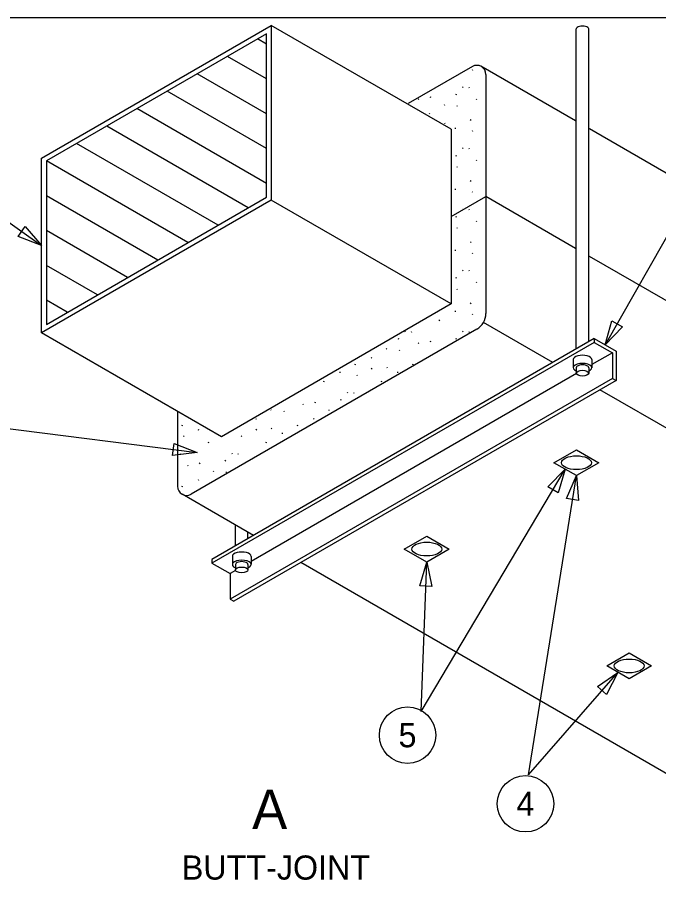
# Model space of a CAD drawing. Extents: x 10110.2 to 10159.4, y 10049.5 to 10140.5.
# Drawn here: x 10126.8 to 10144.51, y 10116.52 to 10140.51 of the extents above; entities that cross this region are included whole.
import ezdxf

# ---------------------------------------------------------------- set-up
doc = ezdxf.new("R2010")
doc.units = 0
for name, color, linetype in [('G-ANNO-SYMB', 7, 'Continuous'), ('G-DETL-GRID', 7, 'Continuous'), ('G-DETL-LINE', 7, 'Continuous'), ('G-DETL-TEXT', 7, 'Continuous')]:
    doc.layers.add(name, color=color, linetype=linetype)

msp = doc.modelspace()

# ---------------------------------------------------------------- linework, layer by layer
at = {"layer": 'G-ANNO-SYMB'}
for centre in [(10137.574, 10120.68), (10140.832, 10118.787)]:
    msp.add_circle(centre, 0.779, dxfattribs=at)
at = {"layer": 'G-DETL-GRID'}
msp.add_lwpolyline([(10110.22, 10140.505), (10159.362, 10140.505), (10159.362, 10095.005), (10110.22, 10095.005)], close=True, dxfattribs=at)
at = {"layer": 'G-DETL-LINE'}
for p, q in [((10138.779, 10137.415), (10133.81, 10140.284)), ((10138.779, 10137.415), (10133.81, 10140.284)), ((10142.233, 10131.347), (10142.233, 10140.184)), ((10142.233, 10131.347), (10142.233, 10140.184)), ((10142.578, 10131.546), (10142.578, 10140.184)), ((10142.578, 10131.546), (10142.578, 10140.184)), ((10133.675, 10139.767), (10133.431, 10139.908)), ((10133.675, 10138.805), (10132.597, 10139.427)), ((10139.363, 10139.147), (10137.591, 10138.124)), ((10139.363, 10139.147), (10137.591, 10138.124)), ((10142.214, 10137.645), (10139.598, 10139.156)), ((10142.214, 10137.645), (10139.598, 10139.156)), ((10133.675, 10137.843), (10131.764, 10138.946)), ((10139.359, 10139.064), (10139.371, 10139.046)), ((10139.359, 10139.064), (10139.371, 10139.046)), ((10139.738, 10138.93), (10139.738, 10132.325)), ((10139.738, 10138.93), (10139.738, 10132.325)), ((10133.675, 10136.88), (10130.931, 10138.465)), ((10138.917, 10138.363), (10138.929, 10138.39)), ((10138.917, 10138.363), (10138.929, 10138.39)), ((10139.094, 10138.585), (10139.106, 10138.567)), ((10139.094, 10138.585), (10139.106, 10138.567)), ((10139.264, 10138.578), (10139.276, 10138.56)), ((10139.264, 10138.578), (10139.276, 10138.56)), ((10137.871, 10138.259), (10137.883, 10138.241)), ((10137.871, 10138.259), (10137.883, 10138.241)), ((10138.207, 10138.294), (10138.219, 10138.321)), ((10138.207, 10138.294), (10138.219, 10138.321)), ((10139.465, 10138.259), (10139.477, 10138.241)), ((10139.465, 10138.259), (10139.477, 10138.241)), ((10133.675, 10135.918), (10130.097, 10137.984)), ((10138.581, 10138.102), (10138.593, 10138.084)), ((10138.581, 10138.102), (10138.593, 10138.084)), ((10138.935, 10138.069), (10138.947, 10138.051)), ((10138.935, 10138.069), (10138.947, 10138.051)), ((10138.167, 10137.857), (10138.179, 10137.839)), ((10138.167, 10137.857), (10138.179, 10137.839)), ((10139.315, 10137.655), (10139.327, 10137.682)), ((10139.315, 10137.655), (10139.327, 10137.682)), ((10133.173, 10135.246), (10129.264, 10137.503)), ((10138.592, 10137.591), (10138.604, 10137.573)), ((10138.592, 10137.591), (10138.604, 10137.573)), ((10138.889, 10137.457), (10138.892, 10137.43)), ((10138.889, 10137.457), (10138.892, 10137.43)), ((10148.395, 10134.077), (10142.598, 10137.424)), ((10148.395, 10134.077), (10142.598, 10137.424)), ((10138.779, 10137.415), (10138.779, 10132.589)), ((10138.779, 10137.415), (10138.779, 10132.589)), ((10139.359, 10137.378), (10139.371, 10137.36)), ((10139.359, 10137.378), (10139.371, 10137.36)), ((10132.339, 10134.765), (10128.431, 10137.021)), ((10138.917, 10136.676), (10138.929, 10136.703)), ((10138.917, 10136.676), (10138.929, 10136.703)), ((10139.094, 10136.898), (10139.106, 10136.88)), ((10139.094, 10136.898), (10139.106, 10136.88)), ((10139.264, 10136.892), (10139.276, 10136.874)), ((10139.264, 10136.892), (10139.276, 10136.874)), ((10131.506, 10134.284), (10127.597, 10136.54)), ((10139.465, 10136.572), (10139.477, 10136.554)), ((10139.465, 10136.572), (10139.477, 10136.554)), ((10138.935, 10136.383), (10138.947, 10136.365)), ((10138.935, 10136.383), (10138.947, 10136.365)), ((10139.315, 10135.969), (10139.327, 10135.996)), ((10139.315, 10135.969), (10139.327, 10135.996)), ((10138.889, 10135.771), (10138.892, 10135.744)), ((10138.889, 10135.771), (10138.892, 10135.744)), ((10130.673, 10133.803), (10127.597, 10135.578)), ((10138.779, 10135.002), (10139.738, 10135.555)), ((10138.779, 10135.002), (10139.738, 10135.555)), ((10139.359, 10135.691), (10139.371, 10135.673)), ((10139.359, 10135.691), (10139.371, 10135.673)), ((10142.214, 10134.125), (10139.738, 10135.555)), ((10142.214, 10134.125), (10139.738, 10135.555)), ((10138.779, 10132.589), (10133.81, 10135.458)), ((10138.779, 10132.589), (10133.81, 10135.458)), ((10139.094, 10135.212), (10139.106, 10135.194)), ((10139.094, 10135.212), (10139.106, 10135.194)), ((10139.264, 10135.205), (10139.276, 10135.187)), ((10139.264, 10135.205), (10139.276, 10135.187)), ((10138.917, 10134.99), (10138.929, 10135.017)), ((10138.917, 10134.99), (10138.929, 10135.017)), ((10139.465, 10134.886), (10139.477, 10134.868)), ((10139.465, 10134.886), (10139.477, 10134.868)), ((10129.839, 10133.321), (10127.597, 10134.616)), ((10138.935, 10134.697), (10138.947, 10134.679)), ((10138.935, 10134.697), (10138.947, 10134.679)), ((10139.315, 10134.283), (10139.327, 10134.31)), ((10139.315, 10134.283), (10139.327, 10134.31)), ((10138.889, 10134.085), (10138.892, 10134.058)), ((10138.889, 10134.085), (10138.892, 10134.058)), ((10139.359, 10134.005), (10139.371, 10133.987)), ((10139.359, 10134.005), (10139.371, 10133.987)), ((10148.947, 10130.239), (10142.598, 10133.904)), ((10148.947, 10130.239), (10142.598, 10133.904)), ((10129.006, 10132.84), (10127.597, 10133.654)), ((10139.094, 10133.526), (10139.106, 10133.508)), ((10139.094, 10133.526), (10139.106, 10133.508)), ((10139.264, 10133.519), (10139.276, 10133.501)), ((10139.264, 10133.519), (10139.276, 10133.501)), ((10138.917, 10133.304), (10138.929, 10133.331)), ((10138.917, 10133.304), (10138.929, 10133.331)), ((10139.465, 10133.2), (10139.477, 10133.182)), ((10139.465, 10133.2), (10139.477, 10133.182)), ((10138.935, 10133.011), (10138.947, 10132.993)), ((10138.935, 10133.011), (10138.947, 10132.993)), ((10128.173, 10132.359), (10127.597, 10132.691)), ((10139.315, 10132.596), (10139.327, 10132.623)), ((10139.315, 10132.596), (10139.327, 10132.623)), ((10138.779, 10132.589), (10132.431, 10128.924)), ((10138.779, 10132.589), (10132.431, 10128.924)), ((10138.889, 10132.398), (10138.892, 10132.371)), ((10138.889, 10132.398), (10138.892, 10132.371)), ((10138.449, 10132.126), (10138.461, 10132.153)), ((10138.449, 10132.126), (10138.461, 10132.153)), ((10139.359, 10132.319), (10139.371, 10132.301)), ((10139.359, 10132.319), (10139.371, 10132.301)), ((10141.582, 10130.971), (10139.671, 10132.075)), ((10141.582, 10130.971), (10139.671, 10132.075)), ((10132.431, 10128.924), (10127.462, 10131.793)), ((10132.431, 10128.924), (10127.462, 10131.793)), ((10139.488, 10131.892), (10131.597, 10127.336)), ((10139.488, 10131.892), (10131.597, 10127.336)), ((10137.499, 10131.84), (10137.511, 10131.822)), ((10137.499, 10131.84), (10137.511, 10131.822)), ((10137.67, 10131.833), (10137.682, 10131.815)), ((10137.67, 10131.833), (10137.682, 10131.815)), ((10139.094, 10131.84), (10139.106, 10131.822)), ((10139.094, 10131.84), (10139.106, 10131.822)), ((10139.264, 10131.833), (10139.276, 10131.815)), ((10139.264, 10131.833), (10139.276, 10131.815)), ((10142.73, 10131.633), (10132.17, 10125.536)), ((10142.73, 10131.633), (10132.17, 10125.536)), ((10142.73, 10131.529), (10132.17, 10125.432)), ((10142.73, 10131.529), (10132.17, 10125.432)), ((10137.322, 10131.617), (10137.334, 10131.644)), ((10137.322, 10131.617), (10137.334, 10131.644)), ((10137.871, 10131.513), (10137.883, 10131.495)), ((10137.871, 10131.513), (10137.883, 10131.495)), ((10138.207, 10131.548), (10138.219, 10131.575)), ((10138.207, 10131.548), (10138.219, 10131.575)), ((10138.917, 10131.617), (10138.929, 10131.644)), ((10138.917, 10131.617), (10138.929, 10131.644)), ((10142.73, 10131.633), (10143.334, 10131.284)), ((10142.73, 10131.633), (10142.73, 10131.529)), ((10142.73, 10131.633), (10143.334, 10131.284)), ((10142.73, 10131.633), (10142.73, 10131.529)), ((10142.73, 10131.529), (10143.23, 10131.24)), ((10142.73, 10131.529), (10143.23, 10131.24)), ((10136.987, 10131.357), (10136.999, 10131.339)), ((10136.987, 10131.357), (10136.999, 10131.339)), ((10137.341, 10131.324), (10137.353, 10131.306)), ((10137.341, 10131.324), (10137.353, 10131.306)), ((10143.23, 10131.24), (10142.665, 10130.914)), ((10143.23, 10131.24), (10142.665, 10130.914)), ((10143.23, 10131.24), (10143.23, 10130.534)), ((10143.23, 10131.24), (10143.23, 10130.534)), ((10143.334, 10131.284), (10143.334, 10130.474)), ((10143.334, 10131.284), (10143.334, 10130.474)), ((10136.572, 10131.111), (10136.584, 10131.093)), ((10136.572, 10131.111), (10136.584, 10131.093)), ((10142.147, 10131.054), (10142.147, 10130.829)), ((10142.147, 10131.054), (10142.147, 10130.829)), ((10142.665, 10131.054), (10142.665, 10130.829)), ((10142.665, 10131.054), (10142.665, 10130.829)), ((10135.7, 10130.712), (10135.703, 10130.685)), ((10135.7, 10130.712), (10135.703, 10130.685)), ((10136.127, 10130.91), (10136.139, 10130.937)), ((10136.127, 10130.91), (10136.139, 10130.937)), ((10136.582, 10130.787), (10136.594, 10130.814)), ((10136.582, 10130.787), (10136.594, 10130.814)), ((10136.998, 10130.845), (10137.01, 10130.827)), ((10136.998, 10130.845), (10137.01, 10130.827)), ((10137.295, 10130.712), (10137.298, 10130.685)), ((10137.295, 10130.712), (10137.298, 10130.685)), ((10137.721, 10130.91), (10137.733, 10130.937)), ((10137.721, 10130.91), (10137.733, 10130.937)), ((10142.233, 10130.829), (10142.233, 10130.679)), ((10142.233, 10130.829), (10142.233, 10130.679)), ((10142.578, 10130.829), (10142.578, 10130.679)), ((10142.578, 10130.829), (10142.578, 10130.679)), ((10143.23, 10130.534), (10132.67, 10124.438)), ((10143.23, 10130.534), (10132.67, 10124.438)), ((10143.334, 10130.474), (10132.774, 10124.377)), ((10143.334, 10130.474), (10132.774, 10124.377)), ((10142.236, 10130.666), (10133.252, 10125.48)), ((10142.236, 10130.666), (10133.252, 10125.48)), ((10135.261, 10130.44), (10135.273, 10130.466)), ((10135.261, 10130.44), (10135.273, 10130.466)), ((10136.17, 10130.632), (10136.182, 10130.614)), ((10136.17, 10130.632), (10136.182, 10130.614)), ((10136.855, 10130.44), (10136.867, 10130.466)), ((10136.855, 10130.44), (10136.867, 10130.466)), ((10143.23, 10130.534), (10143.334, 10130.474)), ((10143.23, 10130.534), (10143.334, 10130.474)), ((10135.905, 10130.153), (10135.917, 10130.135)), ((10135.905, 10130.153), (10135.917, 10130.135)), ((10136.076, 10130.146), (10136.088, 10130.128)), ((10136.076, 10130.146), (10136.088, 10130.128)), ((10156.935, 10122.107), (10142.888, 10130.217)), ((10156.935, 10122.107), (10142.888, 10130.217)), ((10134.682, 10129.827), (10134.694, 10129.809)), ((10134.682, 10129.827), (10134.694, 10129.809)), ((10135.018, 10129.862), (10135.03, 10129.889)), ((10135.018, 10129.862), (10135.03, 10129.889)), ((10135.728, 10129.931), (10135.74, 10129.958)), ((10135.728, 10129.931), (10135.74, 10129.958)), ((10131.222, 10129.621), (10131.222, 10127.553)), ((10131.222, 10129.621), (10131.222, 10127.553)), ((10133.798, 10129.67), (10133.81, 10129.652)), ((10133.798, 10129.67), (10133.81, 10129.652)), ((10134.152, 10129.638), (10134.164, 10129.62)), ((10134.152, 10129.638), (10134.164, 10129.62)), ((10135.392, 10129.67), (10135.404, 10129.652)), ((10135.392, 10129.67), (10135.404, 10129.652)), ((10133.384, 10129.425), (10133.396, 10129.407)), ((10133.384, 10129.425), (10133.396, 10129.407)), ((10134.978, 10129.425), (10134.99, 10129.407)), ((10134.978, 10129.425), (10134.99, 10129.407)), ((10131.344, 10129.224), (10131.356, 10129.251)), ((10131.344, 10129.224), (10131.356, 10129.251)), ((10131.799, 10129.101), (10131.811, 10129.128)), ((10131.799, 10129.101), (10131.811, 10129.128)), ((10133.394, 10129.101), (10133.406, 10129.128)), ((10133.394, 10129.101), (10133.406, 10129.128)), ((10133.809, 10129.159), (10133.821, 10129.141)), ((10133.809, 10129.159), (10133.821, 10129.141)), ((10134.106, 10129.026), (10134.109, 10128.999)), ((10134.106, 10129.026), (10134.109, 10128.999)), ((10134.532, 10129.224), (10134.544, 10129.251)), ((10134.532, 10129.224), (10134.544, 10129.251)), ((10131.387, 10128.946), (10131.399, 10128.928)), ((10131.387, 10128.946), (10131.399, 10128.928)), ((10132.982, 10128.946), (10132.994, 10128.928)), ((10132.982, 10128.946), (10132.994, 10128.928)), ((10132.072, 10128.753), (10132.084, 10128.78)), ((10132.072, 10128.753), (10132.084, 10128.78)), ((10133.666, 10128.753), (10133.678, 10128.78)), ((10133.666, 10128.753), (10133.678, 10128.78)), ((10131.293, 10128.46), (10131.305, 10128.442)), ((10131.293, 10128.46), (10131.305, 10128.442)), ((10132.716, 10128.467), (10132.728, 10128.449)), ((10132.716, 10128.467), (10132.728, 10128.449)), ((10132.887, 10128.46), (10132.899, 10128.442)), ((10132.887, 10128.46), (10132.899, 10128.442)), ((10131.494, 10128.141), (10131.506, 10128.123)), ((10131.494, 10128.141), (10131.506, 10128.123)), ((10131.829, 10128.176), (10131.841, 10128.203)), ((10131.829, 10128.176), (10131.841, 10128.203)), ((10132.539, 10128.245), (10132.551, 10128.272)), ((10132.539, 10128.245), (10132.551, 10128.272)), ((10132.204, 10127.984), (10132.216, 10127.966)), ((10132.204, 10127.984), (10132.216, 10127.966)), ((10132.558, 10127.952), (10132.57, 10127.934)), ((10132.558, 10127.952), (10132.57, 10127.934)), ((10131.789, 10127.739), (10131.801, 10127.721)), ((10131.789, 10127.739), (10131.801, 10127.721)), ((10131.344, 10127.537), (10131.356, 10127.564)), ((10131.344, 10127.537), (10131.356, 10127.564)), ((10133.317, 10126.199), (10131.347, 10127.337)), ((10133.317, 10126.199), (10131.347, 10127.337)), ((10132.821, 10125.912), (10132.821, 10126.485)), ((10132.821, 10125.912), (10132.821, 10126.485)), ((10133.166, 10126.112), (10133.166, 10126.286)), ((10133.166, 10126.112), (10133.166, 10126.286)), ((10132.17, 10125.536), (10132.17, 10125.432)), ((10132.17, 10125.536), (10132.17, 10125.432)), ((10132.17, 10125.536), (10132.17, 10125.432)), ((10132.17, 10125.536), (10132.17, 10125.432)), ((10132.17, 10125.432), (10132.67, 10125.144)), ((10132.17, 10125.432), (10132.67, 10125.144)), ((10132.735, 10125.619), (10132.735, 10125.394)), ((10132.735, 10125.619), (10132.735, 10125.394)), ((10133.252, 10125.619), (10133.252, 10125.394)), ((10133.252, 10125.619), (10133.252, 10125.394)), ((10148.487, 10117.44), (10134.623, 10125.445)), ((10148.487, 10117.44), (10134.623, 10125.445)), ((10132.823, 10125.232), (10132.67, 10125.144)), ((10132.823, 10125.232), (10132.67, 10125.144)), ((10132.821, 10125.394), (10132.821, 10125.244)), ((10132.821, 10125.394), (10132.821, 10125.244)), ((10133.166, 10125.394), (10133.166, 10125.244)), ((10133.166, 10125.394), (10133.166, 10125.244)), ((10132.67, 10125.144), (10132.67, 10124.438)), ((10132.67, 10125.144), (10132.67, 10124.438)), ((10132.67, 10124.438), (10132.774, 10124.377)), ((10132.67, 10124.438), (10132.774, 10124.377))]:
    msp.add_line(p, q, dxfattribs=at)
for points in [[(10127.462, 10136.618), (10133.81, 10140.284), (10133.81, 10135.458), (10127.462, 10131.793)], [(10127.462, 10136.618), (10133.81, 10140.284), (10133.81, 10135.458), (10127.462, 10131.793)], [(10127.597, 10136.54), (10127.597, 10132.027), (10133.675, 10135.536), (10133.675, 10140.049)], [(10127.597, 10136.54), (10127.597, 10132.027), (10133.675, 10135.536), (10133.675, 10140.049)], [(10141.617, 10128.206), (10142.238, 10128.565), (10142.859, 10128.206), (10142.238, 10127.848)], [(10141.617, 10128.206), (10142.238, 10128.565), (10142.859, 10128.206), (10142.238, 10127.848)], [(10137.484, 10125.82), (10138.105, 10126.179), (10138.726, 10125.82), (10138.105, 10125.462)], [(10137.484, 10125.82), (10138.105, 10126.179), (10138.726, 10125.82), (10138.105, 10125.462)], [(10143.074, 10122.593), (10143.695, 10122.952), (10144.316, 10122.593), (10143.695, 10122.234)], [(10143.074, 10122.593), (10143.695, 10122.952), (10144.316, 10122.593), (10143.695, 10122.234)]]:
    msp.add_lwpolyline(points, close=True, dxfattribs=at)
for centre, radius, start, end in [((10139.488, 10138.93), 0.25, 0, 120), ((10139.488, 10138.93), 0.25, 0, 120), ((10139.238, 10132.325), 0.5, 300, 0), ((10139.238, 10132.325), 0.5, 300, 0), ((10131.472, 10127.553), 0.25, 180, 300), ((10131.472, 10127.553), 0.25, 180, 300)]:
    msp.add_arc(centre, radius, start, end, dxfattribs=at)
for centre, major_axis, start_param, end_param in [((10142.406, 10140.185), (-0.173, 0), 3.137491, 6.287287), ((10142.406, 10140.185), (-0.173, 0), 3.137491, 6.287287), ((10142.406, 10130.829), (-0.259, 0), 2.300516, 7.124262), ((10142.406, 10130.829), (-0.259, 0), 2.300516, 7.124262), ((10142.406, 10131.054), (-0.259, 0), 3.137491, 6.287287), ((10142.406, 10131.054), (-0.259, 0), 3.137491, 6.287287), ((10142.406, 10130.829), (-0.173, 0), 3.137491, 6.287287), ((10142.406, 10130.829), (-0.173, 0), 3.137491, 6.287287), ((10132.993, 10125.619), (-0.259, 0), 3.137491, 6.287287), ((10132.993, 10125.619), (-0.259, 0), 3.137491, 6.287287), ((10132.993, 10125.394), (-0.259, 0), 2.300516, 7.124262), ((10132.993, 10125.394), (-0.259, 0), 2.300516, 7.124262), ((10132.993, 10125.394), (-0.173, 0), 3.137491, 6.287287), ((10132.993, 10125.394), (-0.173, 0), 3.137491, 6.287287)]:
    msp.add_ellipse(centre, major_axis=major_axis, ratio=0.460797, start_param=start_param, end_param=end_param, dxfattribs=at)
for centre, major_axis in [((10142.406, 10130.679), (-0.173, 0)), ((10142.406, 10130.679), (-0.173, 0)), ((10142.238, 10128.206), (-0.413, 0)), ((10142.238, 10128.206), (-0.413, 0)), ((10138.105, 10125.82), (-0.413, 0)), ((10138.105, 10125.82), (-0.413, 0)), ((10132.993, 10125.244), (-0.173, 0)), ((10132.993, 10125.244), (-0.173, 0)), ((10143.695, 10122.593), (-0.413, 0)), ((10143.695, 10122.593), (-0.413, 0))]:
    msp.add_ellipse(centre, major_axis=major_axis, ratio=0.460797, dxfattribs=at)
at = {"layer": 'G-DETL-TEXT'}
for p, q in [((10146.44, 10137.459), (10143.032, 10131.459)), ((10146.44, 10137.459), (10143.032, 10131.459)), ((10125.12, 10135.869), (10127.462, 10134.206)), ((10125.258, 10129.309), (10131.765, 10128.489)), ((10125.258, 10129.309), (10131.765, 10128.489)), ((10137.949, 10121.332), (10141.927, 10128.027)), ((10137.949, 10121.332), (10141.927, 10128.027)), ((10140.917, 10119.585), (10142.238, 10127.848)), ((10140.917, 10119.585), (10142.238, 10127.848)), ((10137.949, 10121.332), (10138.105, 10125.462)), ((10137.949, 10121.332), (10138.105, 10125.462)), ((10140.917, 10119.585), (10143.385, 10122.414))]:
    msp.add_line(p, q, dxfattribs=at)
for points in [[(10127.015, 10134.727), (10127.462, 10134.206), (10126.822, 10134.456)], [(10127.015, 10134.727), (10127.462, 10134.206), (10126.822, 10134.456)], [(10143.506, 10131.956), (10143.032, 10131.459), (10143.216, 10132.121)], [(10143.506, 10131.956), (10143.032, 10131.459), (10143.216, 10132.121)], [(10131.124, 10128.738), (10131.765, 10128.489), (10131.083, 10128.407)], [(10131.124, 10128.738), (10131.765, 10128.489), (10131.083, 10128.407)], [(10141.444, 10127.539), (10141.927, 10128.027), (10141.73, 10127.369)], [(10141.444, 10127.539), (10141.927, 10128.027), (10141.73, 10127.369)], [(10141.968, 10127.216), (10142.238, 10127.848), (10142.297, 10127.163)], [(10141.968, 10127.216), (10142.238, 10127.848), (10142.297, 10127.163)], [(10137.914, 10124.802), (10138.105, 10125.462), (10138.247, 10124.789)], [(10137.914, 10124.802), (10138.105, 10125.462), (10138.247, 10124.789)], [(10142.821, 10122.021), (10143.385, 10122.414), (10143.072, 10121.802)], [(10142.821, 10122.021), (10143.385, 10122.414), (10143.072, 10121.802)]]:
    msp.add_lwpolyline(points, close=True, dxfattribs=at)

# ---------------------------------------------------------------- texts
at = {"layer": 'G-ANNO-SYMB'}
for s, p in [('5', (10137.324, 10120.346)), ('4', (10140.582, 10118.453))]:
    msp.add_text(s, height=0.667, dxfattribs=at).set_placement(p)
at = {"layer": 'G-DETL-TEXT'}
for s, height, p in [('A', 1.083, (10133.282, 10118.093)), ('BUTT-JOINT', 0.6667, (10131.338, 10116.691))]:
    msp.add_text(s, height=height, dxfattribs=at).set_placement(p)

doc.saveas('drawing.dxf')
